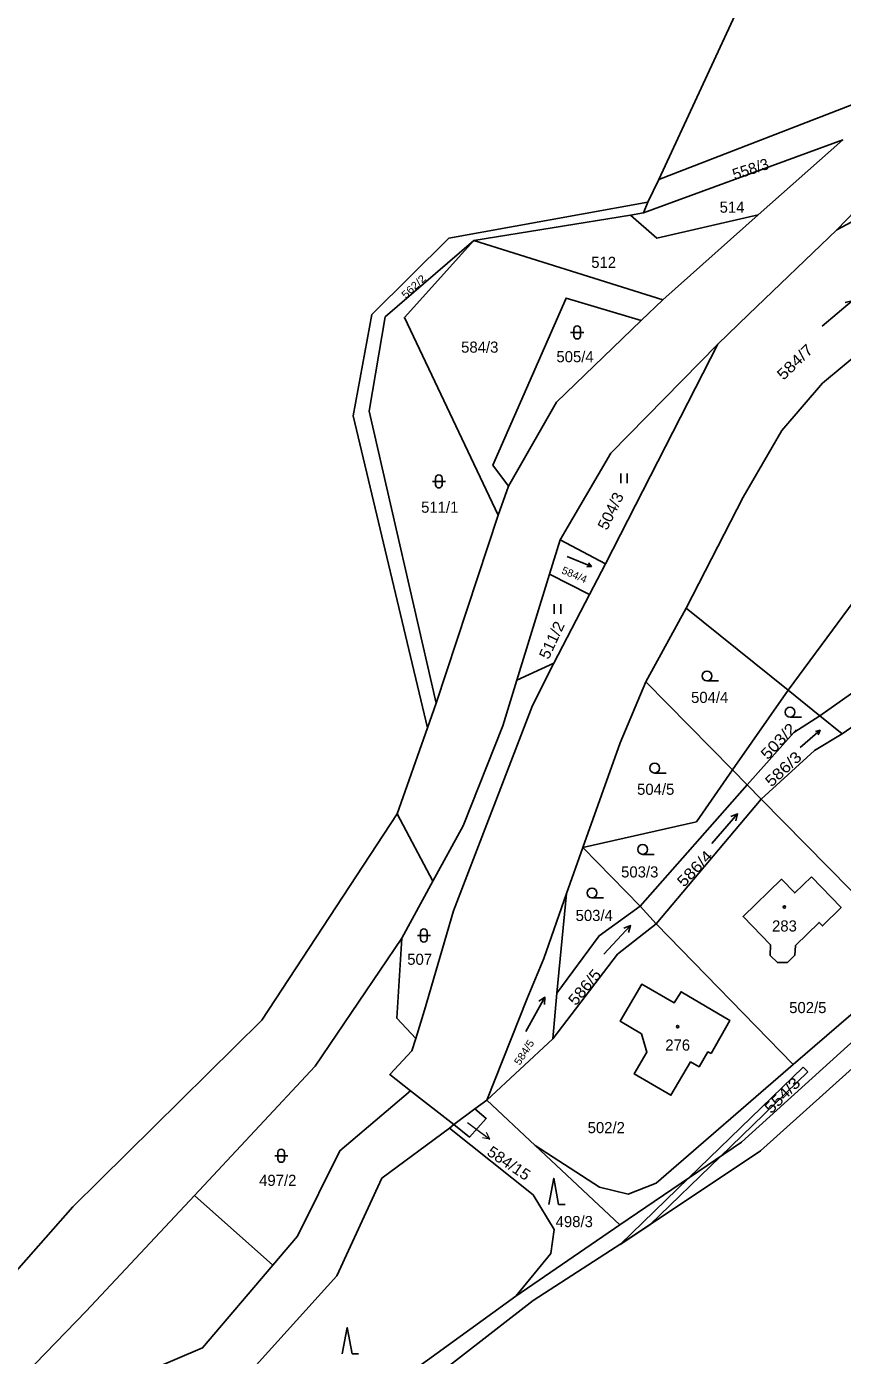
# Model space of a CAD drawing. Extents: x -754445 to -751443, y -1030748 to -1028224.
# Drawn here: x -752772.6 to -752647.9, y -1028727.9 to -1028524.8 of the extents above; entities that cross this region are included whole.
import ezdxf
from ezdxf.enums import TextEntityAlignment as Align

# ---------------------------------------------------------------- set-up
doc = ezdxf.new("R2010")
doc.units = 0
doc.header["$LTSCALE"] = 0.68
for name, color, linetype, lineweight in [('1', 7, 'Continuous', 25), ('13', 7, 'Continuous', 13), ('3', 7, 'Continuous', 25), ('5', 7, 'Continuous', 25), ('7', 7, 'Continuous', 13)]:
    doc.layers.add(name, color=color, linetype=linetype, lineweight=lineweight)
doc.layers.add('2', color=7, linetype='Continuous')

msp = doc.modelspace()

# ---------------------------------------------------------------- linework, layer by layer
at = {"layer": '1'}
for p, q in [((-752655.01, -1028502.82), (-752675.98, -1028548.14)), ((-752675.98, -1028548.14), (-752639.29, -1028533.95)), ((-752677.65, -1028551.6), (-752708.08, -1028557.13)), ((-752675.4, -1028566.53), (-752678.7, -1028569.72)), ((-752722.68, -1028584.29), (-752711.33, -1028631.96)), ((-752698.98, -1028595.03), (-752700.53, -1028599.48)), ((-752709.99, -1028628.2), (-752700.53, -1028599.48)), ((-752692.68, -1028608.47), (-752691.06, -1028603.21)), ((-752692.68, -1028608.47), (-752697.67, -1028624.66)), ((-752686.6, -1028611.56), (-752684.13, -1028606.88)), ((-752692.04, -1028622.09), (-752697.67, -1028624.66)), ((-752677.96, -1028624.94), (-752664.73, -1028638.4)), ((-752656.24, -1028626.23), (-752651.4, -1028630.13)), ((-752651.4, -1028630.13), (-752648, -1028632.86)), ((-752662.48, -1028640.69), (-752660.36, -1028642.84)), ((-752660.36, -1028642.84), (-752676.39, -1028661.94)), ((-752660.36, -1028642.84), (-752636.55, -1028667.05)), ((-752690.08, -1028657.3), (-752687.58, -1028650.25)), ((-752710.52, -1028655.41), (-752715.27, -1028664.13)), ((-752691.55, -1028672.5), (-752690.08, -1028657.3)), ((-752678.86, -1028659.21), (-752676.39, -1028661.94)), ((-752655.45, -1028683.4), (-752636.55, -1028667.05)), ((-752692.17, -1028679.49), (-752691.55, -1028672.5)), ((-752707.33, -1028692.59), (-752713.93, -1028687.42)), ((-752702.27, -1028688.87), (-752694.89, -1028695.8)), ((-752707.98, -1028693.14), (-752707.33, -1028692.59)), ((-752697.84, -1028718.84), (-752692.48, -1028712.29))]:
    msp.add_line(p, q, dxfattribs=at)
for points in [[(-752660.8, -1028553.56), (-752647.89, -1028542.1), (-752678.35, -1028553.28), (-752680.33, -1028553.6)], [(-752675.98, -1028548.14), (-752677.65, -1028551.6), (-752678.35, -1028553.28)], [(-752635.53, -1028550.14), (-752635.08, -1028548.27), (-752641.73, -1028548.5), (-752648.81, -1028555.83)], [(-752648.81, -1028555.83), (-752640.58, -1028551.45), (-752635.53, -1028550.14)], [(-752704.26, -1028557.5), (-752675.4, -1028566.53), (-752660.8, -1028553.56)], [(-752660.8, -1028553.56), (-752676.29, -1028557.11), (-752680.33, -1028553.6), (-752704.26, -1028557.5)], [(-752708.08, -1028557.13), (-752719.83, -1028568.81), (-752722.68, -1028584.29)], [(-752704.26, -1028557.5), (-752717.8, -1028569.17), (-752720.25, -1028583.57), (-752709.99, -1028628.2)], [(-752700.53, -1028599.48), (-752714.85, -1028569.23), (-752704.26, -1028557.5)], [(-752615.82, -1028557.2), (-752639.06, -1028570.02), (-752644.39, -1028573.79), (-752651, -1028579.31), (-752657.18, -1028586.51), (-752663.11, -1028596.69), (-752671.81, -1028613.68), (-752656.24, -1028626.23)], [(-752666.97, -1028573.34), (-752662.31, -1028568.79), (-752648.81, -1028555.83)], [(-752678.7, -1028569.72), (-752690.17, -1028566.29), (-752701.37, -1028591.82), (-752698.98, -1028595.03)], [(-752698.98, -1028595.03), (-752691.61, -1028582.17), (-752678.7, -1028569.72)], [(-752656.24, -1028626.23), (-752632.77, -1028594.44), (-752612.65, -1028569.04)], [(-752601.4, -1028576.11), (-752625.05, -1028611.51), (-752651.4, -1028630.13)], [(-752692.04, -1028622.09), (-752686.6, -1028611.56), (-752692.68, -1028608.47)], [(-752687.58, -1028650.25), (-752681.92, -1028634.23), (-752677.96, -1028624.94), (-752671.81, -1028613.68)], [(-752713.13, -1028679.43), (-752711.77, -1028675.11), (-752707.35, -1028659.93), (-752695.3, -1028628.56), (-752692.04, -1028622.09)], [(-752697.67, -1028624.66), (-752699.83, -1028631.68), (-752705.9, -1028646.95), (-752710.52, -1028655.41)], [(-752656.24, -1028626.23), (-752664.73, -1028638.4), (-752662.48, -1028640.69)], [(-752616.39, -1028646.2), (-752638.21, -1028626.08), (-752648, -1028632.86)], [(-752709.99, -1028628.2), (-752711.33, -1028631.96), (-752715.99, -1028645.08), (-752710.52, -1028655.41)], [(-752662.48, -1028640.69), (-752655.39, -1028632.67), (-752651.4, -1028630.13)], [(-752648, -1028632.86), (-752652.21, -1028635.43), (-752660.36, -1028642.84)], [(-752664.73, -1028638.4), (-752670.25, -1028646.31), (-752687.58, -1028650.25)], [(-752687.58, -1028650.25), (-752678.86, -1028659.21), (-752662.48, -1028640.69)], [(-752604.55, -1028641.14), (-752610.72, -1028650.07), (-752629.83, -1028669.09), (-752660.44, -1028696.62), (-752680.04, -1028709.72), (-752695.17, -1028719.5), (-752712.78, -1028733.15), (-752746.31, -1028767.61), (-752784.35, -1028811.55)], [(-752715.99, -1028645.08), (-752736.64, -1028676.64), (-752765.51, -1028705.15), (-752816.23, -1028762.72)], [(-752690.08, -1028657.3), (-752693.54, -1028667.21), (-752696.13, -1028673.32), (-752702.27, -1028688.87)], [(-752691.55, -1028672.5), (-752685.13, -1028663.73), (-752678.86, -1028659.21)], [(-752681.94, -1028707.94), (-752663.37, -1028695.29), (-752623.97, -1028659.58)], [(-752676.39, -1028661.94), (-752682.3, -1028666.56), (-752692.17, -1028679.49), (-752702.27, -1028688.87)], [(-752694.89, -1028695.8), (-752685.08, -1028702.18), (-752680.66, -1028703.24), (-752676.41, -1028701.53), (-752655.45, -1028683.4), (-752676.39, -1028661.94)], [(-752715.27, -1028664.13), (-752728.5, -1028683.66), (-752746.95, -1028703.41)], [(-752713.13, -1028679.43), (-752716, -1028676.35), (-752715.27, -1028664.13)], [(-752713.93, -1028687.42), (-752717.1, -1028684.93), (-752713.71, -1028681.3), (-752713.13, -1028679.43)], [(-752734.94, -1028714.07), (-752731.18, -1028709.65), (-752724.71, -1028696.59), (-752713.93, -1028687.42)], [(-752707.33, -1028692.59), (-752704.08, -1028690.2), (-752702.27, -1028688.87)], [(-752707.33, -1028692.59), (-752704.9, -1028694.5), (-752702.36, -1028691.68), (-752704.08, -1028690.2)], [(-752707.98, -1028693.14), (-752718.3, -1028700.81), (-752725.18, -1028715.72), (-752740.37, -1028732.54), (-752756.65, -1028738.41), (-752770, -1028754.8), (-752782.2, -1028783.17), (-752771.67, -1028792.14)], [(-752692.48, -1028712.29), (-752691.97, -1028708.62), (-752695.21, -1028703.32), (-752707.98, -1028693.14)], [(-752697.84, -1028718.84), (-752681.94, -1028707.94), (-752694.89, -1028695.8)], [(-752746.95, -1028703.41), (-752763.49, -1028721.12), (-752788.43, -1028746.82), (-752807.82, -1028767.52), (-752817.23, -1028776.57)], [(-752811.45, -1028787.06), (-752788.16, -1028776.57), (-752773.79, -1028748.89), (-752761.36, -1028733.41), (-752745.7, -1028726.7), (-752734.94, -1028714.07), (-752746.95, -1028703.41)], [(-752771.67, -1028792.14), (-752733.85, -1028749.82), (-752714.83, -1028731.17), (-752697.84, -1028718.84)]]:
    msp.add_lwpolyline(points, dxfattribs=at)
for points in [[(-752666.97, -1028573.34), (-752683.32, -1028589.97), (-752691.06, -1028603.21), (-752684.13, -1028606.88)], [(-752652.66, -1028654.74), (-752648.16, -1028659.44), (-752650.98, -1028662.24), (-752651.51, -1028661.7), (-752655.13, -1028665.25), (-752655.19, -1028666.72), (-752656.35, -1028667.82), (-752657.88, -1028667.84), (-752658.99, -1028666.75), (-752658.95, -1028665.1), (-752663.12, -1028660.78), (-752657.24, -1028655.1), (-752655.22, -1028657.2)], [(-752668.02, -1028681.75), (-752668.48, -1028681.49), (-752669.84, -1028683.76), (-752671.13, -1028683.03), (-752674.14, -1028688.12), (-752679.75, -1028684.86), (-752677.82, -1028681.52), (-752678.64, -1028678.74), (-752681.9, -1028676.78), (-752678.61, -1028671.14), (-752673.63, -1028673.97), (-752672.6, -1028672.29), (-752665.15, -1028676.67)]]:
    msp.add_lwpolyline(points, close=True, dxfattribs=at)
at = {"layer": '13'}
msp.add_lwpolyline([(-752653.93, -1028683.8), (-752671.45, -1028700.8), (-752681.88, -1028710.91), (-752677.38, -1028707.94), (-752666.61, -1028697.5), (-752653.23, -1028684.52)], close=True, dxfattribs=at)
at = {"layer": '3'}
for p, q in [((-752689.471, -1028571.531), (-752687.469, -1028571.531)), ((-752688.971, -1028571.031), (-752688.971, -1028572.032)), ((-752687.969, -1028572.032), (-752687.969, -1028571.031)), ((-752710.091, -1028593.801), (-752710.091, -1028594.802)), ((-752709.089, -1028594.802), (-752709.089, -1028593.801)), ((-752681.821, -1028594.59), (-752681.821, -1028593.09)), ((-752680.82, -1028594.59), (-752680.82, -1028593.09)), ((-752710.591, -1028594.301), (-752708.589, -1028594.301)), ((-752686.278, -1028607.303), (-752687.011, -1028607.369)), ((-752691.961, -1028614.54), (-752691.961, -1028613.04)), ((-752690.96, -1028614.54), (-752690.96, -1028613.04)), ((-752668.623, -1028624.8), (-752666.873, -1028624.8)), ((-752655.943, -1028630.32), (-752654.193, -1028630.32)), ((-752651.351, -1028632.328), (-752651.624, -1028633.011)), ((-752676.623, -1028638.87), (-752674.873, -1028638.87)), ((-752663.954, -1028645.119), (-752664.217, -1028646.185)), ((-752678.453, -1028651.3), (-752676.703, -1028651.3)), ((-752686.193, -1028657.95), (-752684.443, -1028657.95)), ((-752712.381, -1028663.201), (-752712.381, -1028664.202)), ((-752711.379, -1028664.202), (-752711.379, -1028663.201)), ((-752680.306, -1028662.189), (-752680.606, -1028663.246)), ((-752712.881, -1028663.701), (-752710.879, -1028663.701)), ((-752693.4, -1028673.125), (-752693.435, -1028674.223)), ((-752734.681, -1028697.361), (-752732.679, -1028697.361)), ((-752734.181, -1028696.861), (-752734.181, -1028697.862)), ((-752733.179, -1028697.862), (-752733.179, -1028696.861)), ((-752691.3, -1028704.81), (-752690.304, -1028704.81)), ((-752722.85, -1028727.62), (-752721.854, -1028727.62))]:
    msp.add_line(p, q, dxfattribs=at)
for points in [[(-752651.059, -1028570.564), (-752646.463, -1028566.707), (-752647.534, -1028566.951)], [(-752690.005, -1028605.797), (-752686.278, -1028607.303), (-752686.759, -1028606.746)], [(-752654.385, -1028634.965), (-752651.351, -1028632.328), (-752652.065, -1028632.504)], [(-752667.89, -1028649.647), (-752663.954, -1028645.119), (-752664.974, -1028645.527)], [(-752684.398, -1028666.577), (-752680.306, -1028662.189), (-752681.339, -1028662.562)], [(-752696.309, -1028678.373), (-752693.4, -1028673.125), (-752694.312, -1028673.737)], [(-752691.3, -1028704.81), (-752692.05, -1028700.81), (-752692.8, -1028704.81)], [(-752722.85, -1028727.62), (-752723.6, -1028723.62), (-752724.35, -1028727.62)]]:
    msp.add_lwpolyline(points, dxfattribs=at)
for centre in [(-752668.6229, -1028624.0498), (-752655.9429, -1028629.5698), (-752676.6229, -1028638.1198), (-752678.4529, -1028650.5498), (-752686.1929, -1028657.1998)]:
    msp.add_circle(centre, 0.75, dxfattribs=at)
for centre, start, end in [((-752688.47, -1028571.0309), 0, 180), ((-752688.47, -1028572.0309), 180, 359.98789), ((-752709.59, -1028593.8009), 0, 180), ((-752709.59, -1028594.8009), 180, 359.98789), ((-752711.88, -1028663.2009), 0, 180), ((-752711.88, -1028664.2009), 180, 359.98789), ((-752733.68, -1028696.8609), 0, 180), ((-752733.68, -1028697.8609), 180, 359.98789)]:
    msp.add_arc(centre, 0.5, start, end, dxfattribs=at)
at = {"layer": '5'}
for centre in [(-752656.8068, -1028659.3492), (-752673.1168, -1028677.6192)]:
    msp.add_circle(centre, 0.175, dxfattribs=at)
at = {"layer": '7'}
msp.add_line((-752701.823, -1028694.826), (-752702.322, -1028693.823), dxfattribs=at)
msp.add_lwpolyline([(-752705.22, -1028692.27), (-752704.22, -1028693.02), (-752701.823, -1028694.826), (-752702.924, -1028694.623)], dxfattribs=at)

# ---------------------------------------------------------------- texts
at = {"layer": '2'}
msp.add_text('558/3', height=1.7, rotation=18, dxfattribs=at).set_placement((-752661.7112, -1028547.3711), align=Align.CENTER)
for s, p in [('514', (-752664.809, -1028553.24)), ('512', (-752684.419, -1028561.67)), ('584/3', (-752703.35, -1028574.63)), ('505/4', (-752688.79, -1028576.09)), ('511/1', (-752709.46, -1028599.09)), ('504/4', (-752668.22, -1028628.16)), ('504/5', (-752676.47, -1028642.2)), ('503/3', (-752678.91, -1028654.83)), ('503/4', (-752685.86, -1028661.48)), ('283', (-752656.799, -1028663.09)), ('507', (-752712.529, -1028668.18)), ('502/5', (-752653.23, -1028675.56)), ('276', (-752673.109, -1028681.29)), ('502/2', (-752684.02, -1028693.91)), ('497/2', (-752734.21, -1028701.97)), ('498/3', (-752688.91, -1028708.27))]:
    msp.add_text(s, height=1.7, dxfattribs=at).set_placement(p, align=Align.CENTER)
for s, height, rotation, width, p in [('562/2', 1.14, 43, 1.15, (-752713.0617, -1028564.935)), ('584/7', 1.7, 44, 1.15, (-752654.6055, -1028576.6704)), ('504/3', 1.7, 64, 1.05, (-752682.5942, -1028599.1941)), ('584/4', 1.14, 337, 1.05, (-752689.1132, -1028609.0879)), ('511/2', 1.7, 65, 1.05, (-752691.5771, -1028618.9087)), ('503/2', 1.7, 46, 1.15, (-752657.1084, -1028634.5965)), ('586/3', 1.7, 43, 1.15, (-752656.4032, -1028638.8712)), ('586/4', 1.7, 46, 1.15, (-752669.8984, -1028654.0665)), ('586/5', 1.7, 50, 1.1, (-752686.6828, -1028672.1414)), ('584/5', 1.14, 57, 1.1, (-752696.0968, -1028681.8634)), ('554/3', 1.7, 45, 1.15, (-752656.518, -1028688.72))]:
    msp.add_text(s, height=height, rotation=rotation, dxfattribs=dict(at, width=width)).set_placement(p, align=Align.CENTER)
at = {"layer": '2', "width": 1.05}
msp.add_text('584/15', height=1.7, rotation=326, dxfattribs=at).set_placement((-752702.394, -1028697.158))

doc.saveas('drawing.dxf')
